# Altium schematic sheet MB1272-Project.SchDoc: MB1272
size A4; Date: Not used; ApprovedBy: Not used; CheckedBy: Not used; Author: Not used; CompanyName: STMicroelectronics; DrawnBy: Not used; Engineer: Not used; Organization: Not used; Address1: Not used; Address2: Not used; Address3: Not used; Address4: Not used; DocumentNumber: Not used; Revision: Not used; SheetNumber: 1; SheetTotal: 15
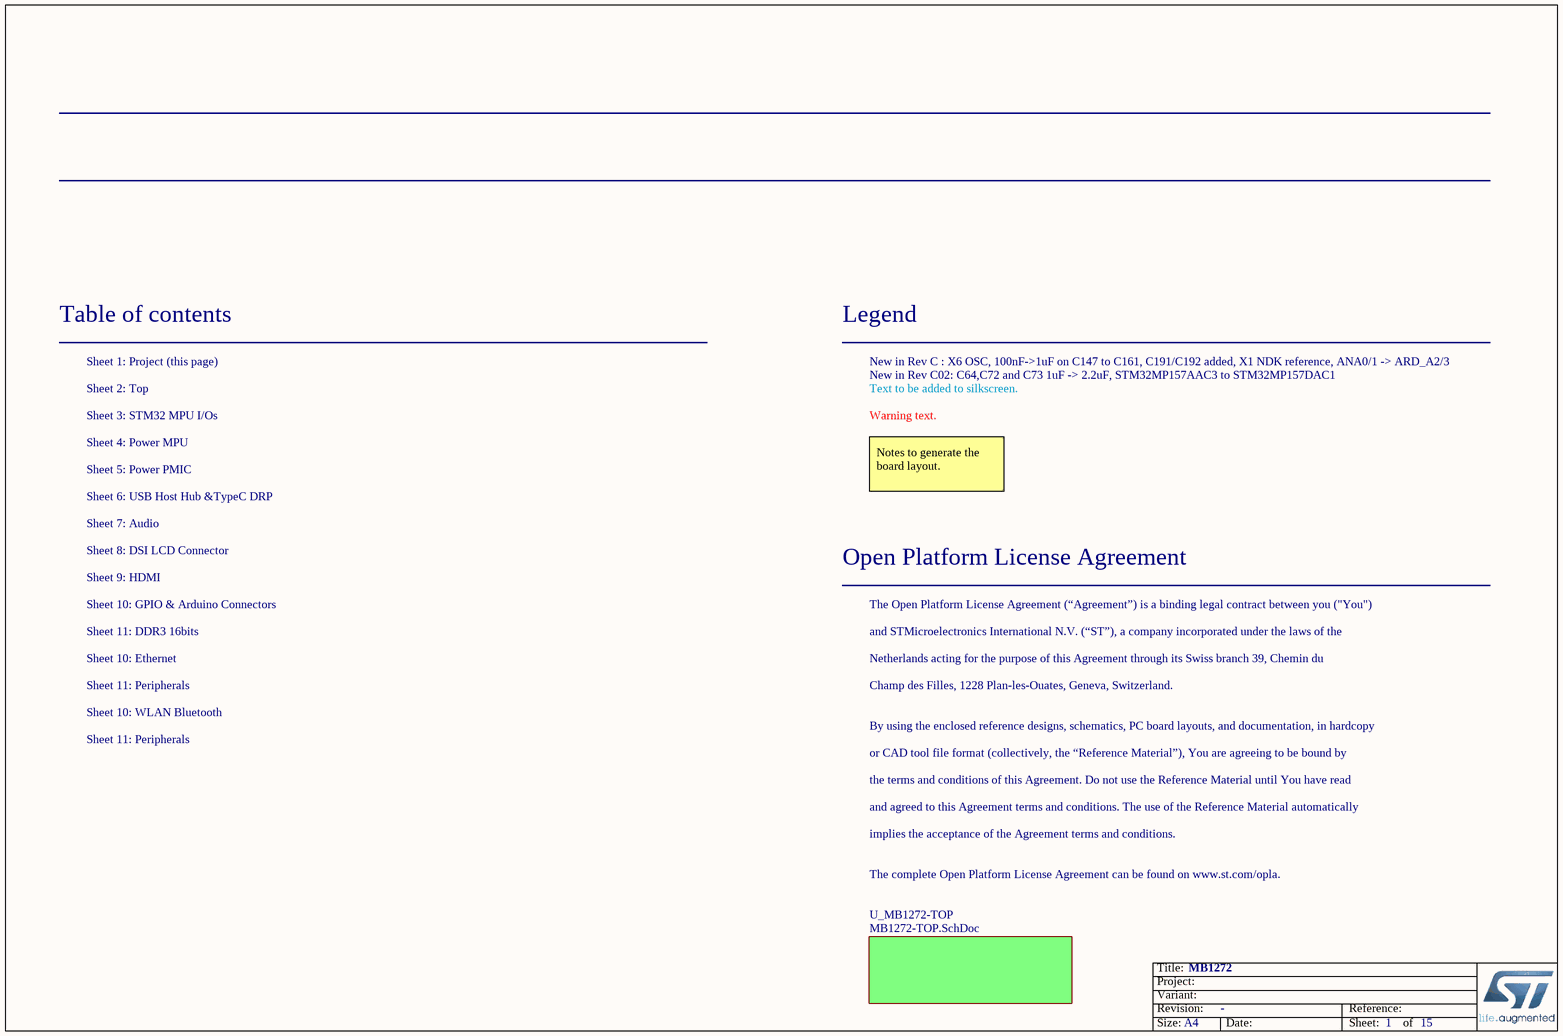
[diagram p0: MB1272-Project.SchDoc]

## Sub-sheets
U_MB1272-TOP = MB1272-TOP.SchDoc: no entries

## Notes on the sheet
- Table of contents
- Sheet 1: Project (this page)
- Legend
- New in Rev C : X6 OSC, 100nF->1uF on C147 to C161, C191/C192 added, X1 NDK reference, ANA0/1 -> ARD_A2/3
- New in Rev C02: C64,C72 and C73 1uF -> 2.2uF, STM32MP157AAC3 to STM32MP157DAC1
- Sheet 2: Top
- Sheet 3: STM32 MPU I/Os
- Sheet 4: Power MPU
- Text to be added to silkscreen.
- Warning text.
- Sheet 6: USB Host Hub &TypeC DRP
- Sheet 5: Power PMIC
- Notes to generate the board layout.
- Sheet 7: Audio
- Sheet 9: HDMI
- Sheet 8: DSI LCD Connector
- Open Platform License Agreement
- Sheet 10: GPIO & Arduino Connectors
- Sheet 11: DDR3 16bits
- The Open Platform License Agreement (“Agreement”) is a binding legal contract between you ("You")
- and STMicroelectronics International N.V. (“ST”), a company incorporated under the laws of the
- Sheet 10: Ethernet
- Sheet 11: Peripherals
- Sheet 10: WLAN Bluetooth
- Netherlands acting for the purpose of this Agreement through its Swiss branch 39, Chemin du
- Champ des Filles, 1228 Plan-les-Ouates, Geneva, Switzerland.
- By using the enclosed reference designs, schematics, PC board layouts, and documentation, in hardcopy
- or CAD tool file format (collectively, the “Reference Material”), You are agreeing to be bound by
- the terms and conditions of this Agreement. Do not use the Reference Material until You have read
- and agreed to this Agreement terms and conditions. The use of the Reference Material automatically
- implies the acceptance of the Agreement terms and conditions.
- The complete Open Platform License Agreement can be found on www.st.com/opla.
